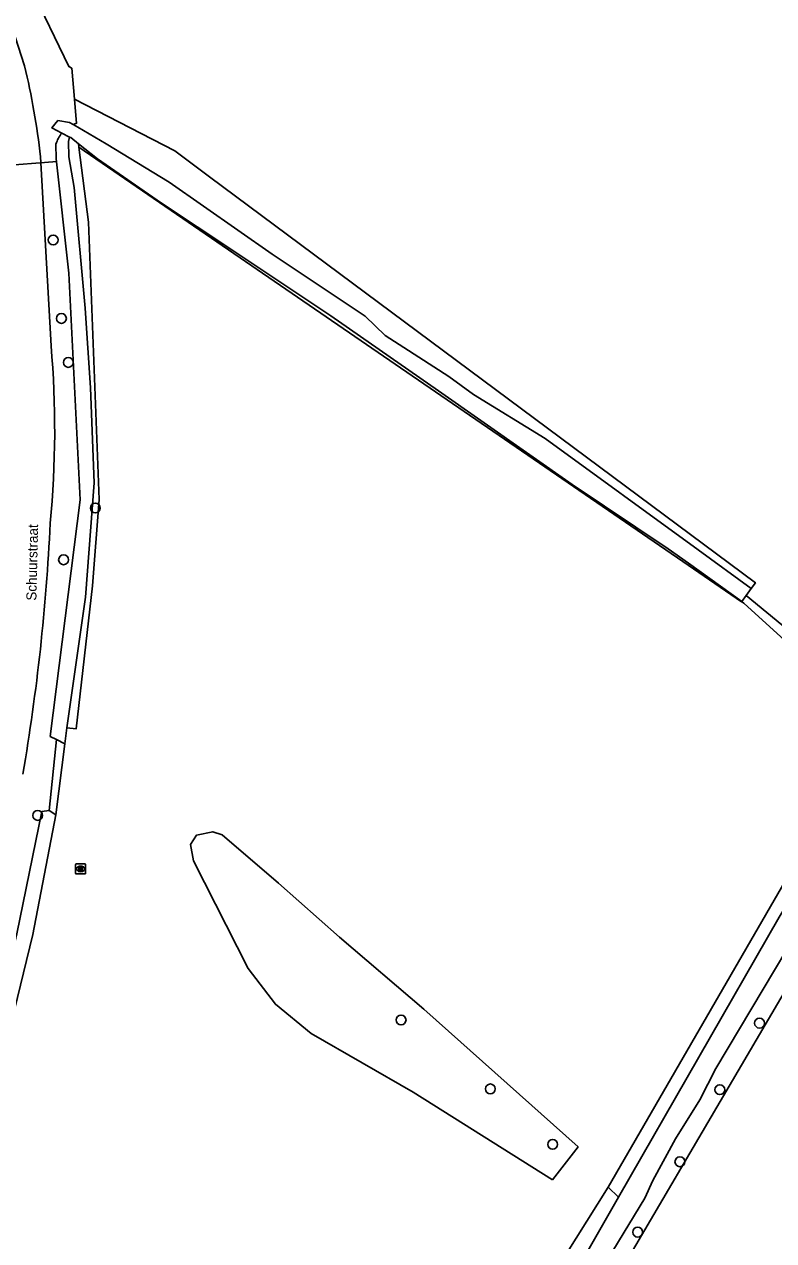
# Model space of a CAD drawing. Extents: x 164494 to 166241, y 382475 to 384494.
# Drawn here: x 165228.9 to 165303.3, y 383751 to 383871.8 of the extents above; entities that cross this region are included whole.
import ezdxf

# ---------------------------------------------------------------- set-up
doc = ezdxf.new("R2010")
doc.units = 0
for name, color, linetype in [('IMGEO_Boom', 7, 'Continuous'), ('IMGEO_Bouwland', 7, 'Continuous'), ('IMGEO_Duiker', 7, 'Continuous'), ('IMGEO_Gemengd_bos', 7, 'Continuous'), ('IMGEO_Hek', 7, 'Continuous'), ('IMGEO_Loofbos', 7, 'Continuous'), ('IMGEO_Openbare_ruimte_label', 7, 'Continuous'), ('IMGEO_Rijbaan_lokaal_gesloten', 7, 'Continuous'), ('IMGEO_Rioolput', 7, 'Continuous'), ('IMGEO_Waterloop', 7, 'Continuous')]:
    doc.layers.add(name, color=color, linetype=linetype)

msp = doc.modelspace()

# ---------------------------------------------------------------- linework, layer by layer
at = {"layer": 'IMGEO_Boom'}
for centre in [(165231.73, 383850.41), (165232.55, 383842.61), (165233.23, 383838.24), (165235.92, 383823.78), (165232.76, 383818.64), (165230.19, 383793.24), (165266.3, 383772.93), (165301.91, 383772.61), (165275.17, 383766.08), (165297.97, 383766), (165281.36, 383760.57), (165294, 383758.84), (165289.81, 383751.85)]:
    msp.add_circle(centre, 0.489, dxfattribs=at)
at = {"layer": 'IMGEO_Bouwland'}
for points in [[(165233.86, 383864.4), (165233.6, 383867.46), (165233.28, 383867.63), (165229.49, 383875.54), (165229.15, 383884.65)], [(165233.1, 383801.95), (165234, 383801.83), (165235.63, 383816.06), (165236.31, 383824.62), (165235.23, 383852.16), (165234.27, 383859.63)], [(165300.59, 383815.1), (165304.71, 383811.7)], [(165232, 383793.29), (165232.88, 383800.37)], [(165286.89, 383756.32), (165263.01, 383718.28), (165264.07, 383715.83)]]:
    msp.add_lwpolyline(points, dxfattribs=at)
at = {"layer": 'IMGEO_Duiker'}
for points in [[(165226.15, 383857.73), (165232.12, 383858.21)], [(165232.05, 383800.79), (165231.32, 383793.72)]]:
    msp.add_lwpolyline(points, dxfattribs=at)
at = {"layer": 'IMGEO_Gemengd_bos'}
for points in [[(165313.21, 383802.17), (165307.58, 383792.13), (165307.27, 383791.58), (165286.89, 383756.32)], [(165286.89, 383756.32), (165287.91, 383755.34)]]:
    msp.add_lwpolyline(points, dxfattribs=at)
at = {"layer": 'IMGEO_Hek'}
for points in [[(165234.27, 383859.63), (165294.29, 383818.46), (165300.34, 383814.32), (165313.5, 383802.36), (165307.58, 383792.13)], [(165268.68, 383714.94), (165289.28, 383750), (165315.43, 383794.51), (165317.99, 383798.04)], [(165307.27, 383791.58), (165286.89, 383756.32)]]:
    msp.add_lwpolyline(points, dxfattribs=at)
at = {"layer": 'IMGEO_Loofbos'}
for points in [[(165233.86, 383864.4), (165234.06, 383861.99)], [(165301.09, 383815.8), (165301.5, 383816.36), (165247.27, 383856.67), (165243.81, 383859.25), (165233.86, 383864.4)], [(165234.27, 383859.63), (165234.24, 383859.96)], [(165234.27, 383859.63), (165294.29, 383818.46), (165300.13, 383814.46), (165300.16, 383814.51)], [(165268.68, 383714.94), (165289.28, 383750), (165315.43, 383794.51), (165317.99, 383798.04)], [(165281.33, 383757.05), (165283.89, 383760.31), (165268.57, 383773.99), (165260.17, 383781.14), (165254.13, 383786.5), (165248.52, 383791.32), (165247.58, 383791.63), (165245.96, 383791.28), (165245.39, 383790.35), (165245.67, 383788.73), (165251.1, 383778.04), (165253.82, 383774.49), (165257.37, 383771.58), (165267.51, 383765.77), (165281.33, 383757.05)]]:
    msp.add_lwpolyline(points, dxfattribs=at)
msp.add_arc((165234.99, 383858.98), 3.16, 107.244, 113.6396, dxfattribs=at)
at = {"layer": 'IMGEO_Rijbaan_lokaal_gesloten'}
for points in [[(165228.89, 383867.71), (165227.07, 383873.35)], [(165231.52, 383839.89), (165230.48, 383858.67)]]:
    msp.add_lwpolyline(points, dxfattribs=at)
for centre, radius, start, end in [((165153.74, 383849.85), 77.25, 6.5546, 13.371), ((165136.16, 383831.55), 95.72, 354.4348, 4.9996), ((165026.07, 383832.07), 205.6, 350.2713, 357.2677)]:
    msp.add_arc(centre, radius, start, end, dxfattribs=at)
at = {"layer": 'IMGEO_Rioolput'}
for p, q in [((165233.95, 383787.5), (165233.95, 383788.36)), ((165234.03, 383788.43), (165234.88, 383788.43)), ((165234.95, 383788.36), (165234.95, 383787.5)), ((165234.88, 383787.43), (165234.03, 383787.43)), ((165234.44, 383788.21), (165234.46, 383788.21)), ((165234.46, 383787.65), (165234.44, 383787.65))]:
    msp.add_line(p, q, dxfattribs=at)
for points in [[(165233.95, 383787.5), (165233.95, 383788.36)], [(165234.03, 383788.43), (165234.88, 383788.43)], [(165234.95, 383788.36), (165234.95, 383787.5)], [(165234.88, 383787.43), (165234.03, 383787.43)], [(165234.54, 383788.13), (165234.29, 383788.13), (165234.29, 383787.73)], [(165234.29, 383787.73), (165234.41, 383787.73), (165234.41, 383787.89), (165234.42, 383787.89)], [(165234.47, 383788.05), (165234.41, 383788.05), (165234.41, 383787.97)], [(165234.41, 383787.97), (165234.46, 383787.97)], [(165234.47, 383787.86), (165234.54, 383787.73), (165234.68, 383787.73), (165234.62, 383787.86)]]:
    msp.add_lwpolyline(points, dxfattribs=at)
for centre, radius, start, end in [((165234.03, 383788.36), 0.0765, 91.552, 178.448), ((165234.03, 383788.36), 0.0765, 91.552, 178.448), ((165234.88, 383788.36), 0.0765, 1.552, 88.448), ((165234.88, 383788.36), 0.0765, 1.552, 88.448), ((165234.03, 383787.51), 0.0765, 181.552, 268.448), ((165234.03, 383787.51), 0.0765, 181.552, 268.448), ((165234.42, 383787.84), 0.0533, 26.0293, 88.6989), ((165234.45, 383788.16), 0.19, 274.7715, 282.9687), ((165234.47, 383787.95), 0.0964, 77.0061, 93.1865), ((165234.49, 383788.01), 0.0378, 276.6634, 79.6772), ((165234.54, 383788.02), 0.109, 350.3612, 89.416), ((165234.54, 383788.02), 0.112, 277.5842, 350.9817), ((165234.52, 383787.8), 0.108, 29.5134, 73.7905), ((165234.88, 383787.51), 0.0765, 271.552, 358.448), ((165234.88, 383787.51), 0.0765, 271.552, 358.448)]:
    msp.add_arc(centre, radius, start, end, dxfattribs=at)
for centre, major_axis, ratio, start_param, end_param in [((165234.44, 383787.93), (-0.387, 0.002), 0.722429, 4.712389, 7.853982), ((165234.46, 383787.93), (-0.39, 0.002), 0.717154, 1.570796, 4.712389)]:
    msp.add_ellipse(centre, major_axis=major_axis, ratio=ratio, start_param=start_param, end_param=end_param, dxfattribs=at)
at = {"layer": 'IMGEO_Waterloop'}
for points in [[(165233.73, 383861.87), (165233.36, 383862.09), (165232.2, 383862.28), (165231.61, 383861.54), (165232.6, 383861.03)], [(165233.36, 383860.63), (165232.6, 383861.03)], [(165301.09, 383815.8), (165295.83, 383819.63), (165280.62, 383830.68), (165273.49, 383835.04), (165271.06, 383836.84), (165266.57, 383839.74), (165264.71, 383840.91), (165262.72, 383842.83), (165253.49, 383848.99), (165243.27, 383856.15), (165236.98, 383859.96), (165234.17, 383861.61), (165233.73, 383861.87)], [(165232, 383859.92), (165232.04, 383858.45), (165233.28, 383847.12), (165234.4, 383824.58), (165231.43, 383801.1), (165232.05, 383800.79), (165232.88, 383800.37)], [(165233.1, 383801.95), (165234.93, 383814.91), (165235.8, 383826.28), (165235.44, 383835.72), (165234.9, 383843.63), (165233.82, 383855.62), (165233.27, 383858.67), (165233.24, 383860.19), (165233.36, 383860.63)], [(165234.24, 383859.96), (165233.47, 383860.57), (165233.36, 383860.63)], [(165234.24, 383859.96), (165236.14, 383858.47), (165242.5, 383854.05), (165249.59, 383849.36), (165259.32, 383842.88), (165270.03, 383835.41), (165283.29, 383826.11), (165292.83, 383819.73), (165294.86, 383818.29), (165300.16, 383814.51)], [(165300.16, 383814.51), (165300.59, 383815.1)], [(165300.59, 383815.1), (165301.09, 383815.8)], [(165232.88, 383800.37), (165233.1, 383801.95)], [(165232, 383793.29), (165231.32, 383793.72), (165230.62, 383793.62), (165228.12, 383781.47), (165224.06, 383764.09), (165221.07, 383750), (165212.92, 383706.55), (165211.44, 383695.56), (165210.82, 383688.54), (165210.23, 383683.79), (165209.57, 383680.75), (165209.1, 383675.95), (165208.26, 383669.95), (165207.95, 383667.8)], [(165209.32, 383667.69), (165209.55, 383669.75), (165209.51, 383671.77), (165210.36, 383676.67), (165214.71, 383707.74), (165222.75, 383750), (165225.36, 383763.73), (165229.71, 383781.42), (165232, 383793.29)], [(165308.54, 383790.83), (165303.88, 383783.14), (165287.91, 383755.34)], [(165269.51, 383719.11), (165273.67, 383725.83), (165287.33, 383750), (165290.53, 383755.21), (165291.32, 383756.98), (165293.57, 383761.11), (165295.98, 383764.99), (165297.57, 383768.12), (165310.45, 383789.71)], [(165287.91, 383755.34), (165284.85, 383750), (165281.37, 383743.95), (165277.58, 383738.26), (165270.63, 383727.09), (165266.57, 383720.27)]]:
    msp.add_lwpolyline(points, dxfattribs=at)
msp.add_arc((165235, 383859.02), 3.13, 140.0681, 163.1132, dxfattribs=at)

# ---------------------------------------------------------------- texts
at = {"layer": 'IMGEO_Openbare_ruimte_label'}
msp.add_text('Schuurstraat', height=1, rotation=88.6824, dxfattribs=at).set_placement((165230.06, 383814.57))

doc.saveas('drawing.dxf')
